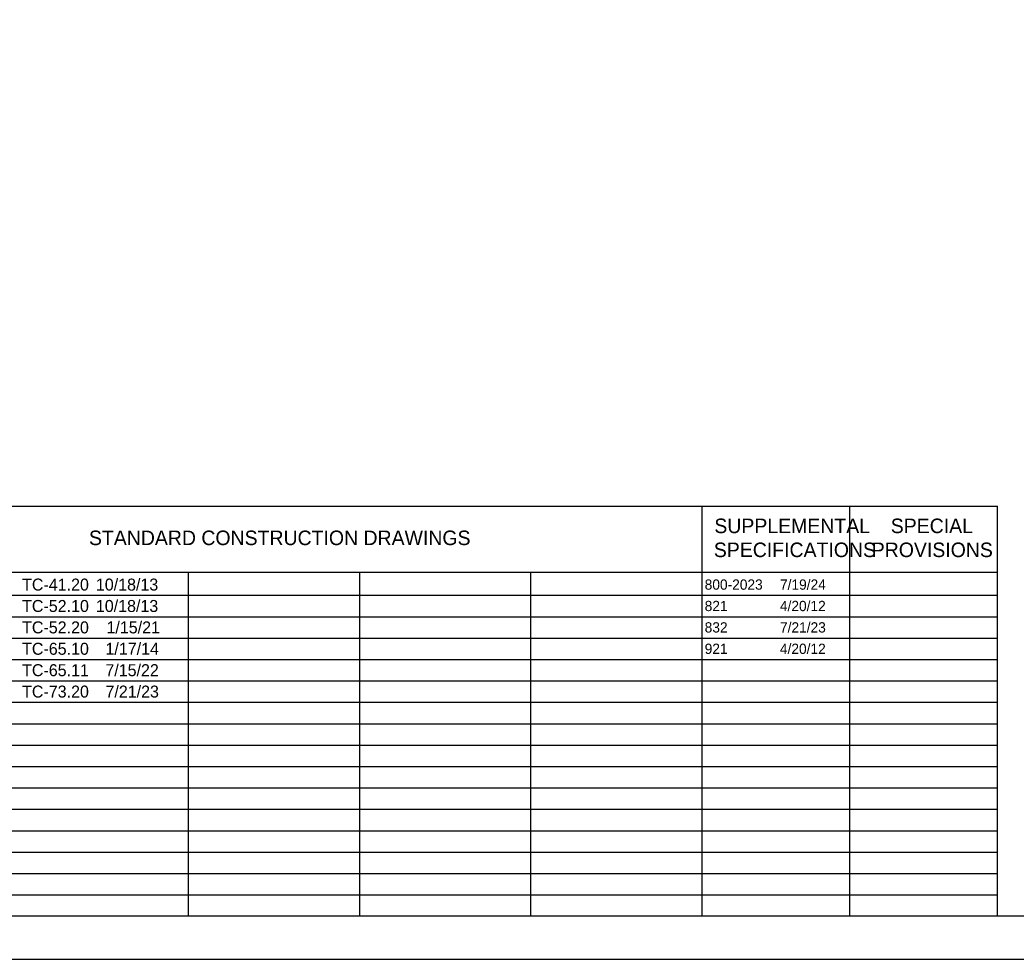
# Model space of a CAD drawing. Extents: x 0 to 34, y 0 to 22.
# Drawn here: x 12.18 to 23.82, y 0 to 10.97 of the extents above; entities that cross this region are included whole.
import ezdxf

# ---------------------------------------------------------------- set-up
doc = ezdxf.new("R2010")
doc.units = 0
for name, color, linetype in [('SH_Border', 7, 'Continuous'), ('SH_Cut_Line', 7, 'Continuous'), ('SH_Data', 7, 'Continuous'), ('SH_Text', 7, 'Continuous')]:
    doc.layers.add(name, color=color, linetype=linetype)

msp = doc.modelspace()

# ---------------------------------------------------------------- linework, layer by layer
at = {"layer": 'SH_Border'}
msp.add_lwpolyline([(1.5, 21.5), (33.5, 21.5), (33.5, 0.5), (1.5, 0.5)], close=True, dxfattribs=at)
at = {"layer": 'SH_Cut_Line'}
msp.add_lwpolyline([(0, 0), (34, 0), (34, 22), (0, 22)], close=True, dxfattribs=at)
at = {"layer": 'SH_Data'}
for p, q in [((10.15, 5.292), (23.6, 5.292)), ((20.15, 0.5), (20.15, 5.292)), ((21.875, 0.5), (21.875, 5.292)), ((23.6, 0.5), (23.6, 5.292)), ((10.15, 4.521), (23.6, 4.521)), ((14.15, 0.5), (14.15, 4.521)), ((16.15, 0.5), (16.15, 4.521)), ((18.15, 0.5), (18.15, 4.521)), ((10.15, 4.25), (23.6, 4.25)), ((10.15, 4), (23.6, 4)), ((10.15, 3.75), (23.6, 3.75)), ((10.15, 3.5), (23.6, 3.5)), ((10.15, 3.25), (23.6, 3.25)), ((10.15, 3), (23.6, 3)), ((10.15, 2.75), (23.6, 2.75)), ((10.15, 2.5), (23.6, 2.5)), ((10.15, 2.25), (23.6, 2.25)), ((10.15, 2), (23.6, 2)), ((10.15, 1.75), (23.6, 1.75)), ((10.15, 1.5), (23.6, 1.5)), ((10.15, 1.25), (23.6, 1.25)), ((10.15, 1), (23.6, 1)), ((10.15, 0.75), (23.6, 0.75))]:
    msp.add_line(p, q, dxfattribs=at)

# ---------------------------------------------------------------- texts
at = {"layer": 'SH_Text'}
for s, height, p in [('SUPPLEMENTAL', 0.17, (20.293, 4.976)), ('SPECIAL', 0.17, (22.354, 4.976)), ('STANDARD CONSTRUCTION DRAWINGS', 0.17, (12.986, 4.836)), ('SPECIFICATIONS', 0.17, (20.287, 4.696)), ('PROVISIONS', 0.17, (22.132, 4.696)), ('TC-41.20', 0.14, (12.205, 4.305)), ('10/18/13', 0.14, (13.067, 4.305)), ('800-2023', 0.12, (20.18, 4.315)), ('7/19/24', 0.12, (21.06, 4.315)), ('TC-52.10', 0.14, (12.205, 4.055)), ('10/18/13', 0.14, (13.067, 4.055)), ('4/20/12', 0.12, (21.059, 4.065)), ('821', 0.12, (20.18, 4.065)), ('TC-52.20', 0.14, (12.205, 3.805)), ('1/15/21', 0.14, (13.191, 3.805)), ('832', 0.12, (20.18, 3.815)), ('7/21/23', 0.12, (21.06, 3.815)), ('TC-65.10', 0.14, (12.205, 3.555)), ('1/17/14', 0.14, (13.179, 3.555)), ('921', 0.12, (20.18, 3.565)), ('4/20/12', 0.12, (21.059, 3.565)), ('TC-65.11', 0.14, (12.205, 3.305)), ('7/15/22', 0.14, (13.178, 3.305)), ('TC-73.20', 0.14, (12.205, 3.055)), ('7/21/23', 0.14, (13.179, 3.055))]:
    msp.add_text(s, height=height, dxfattribs=at).set_placement(p)

doc.saveas('drawing.dxf')
